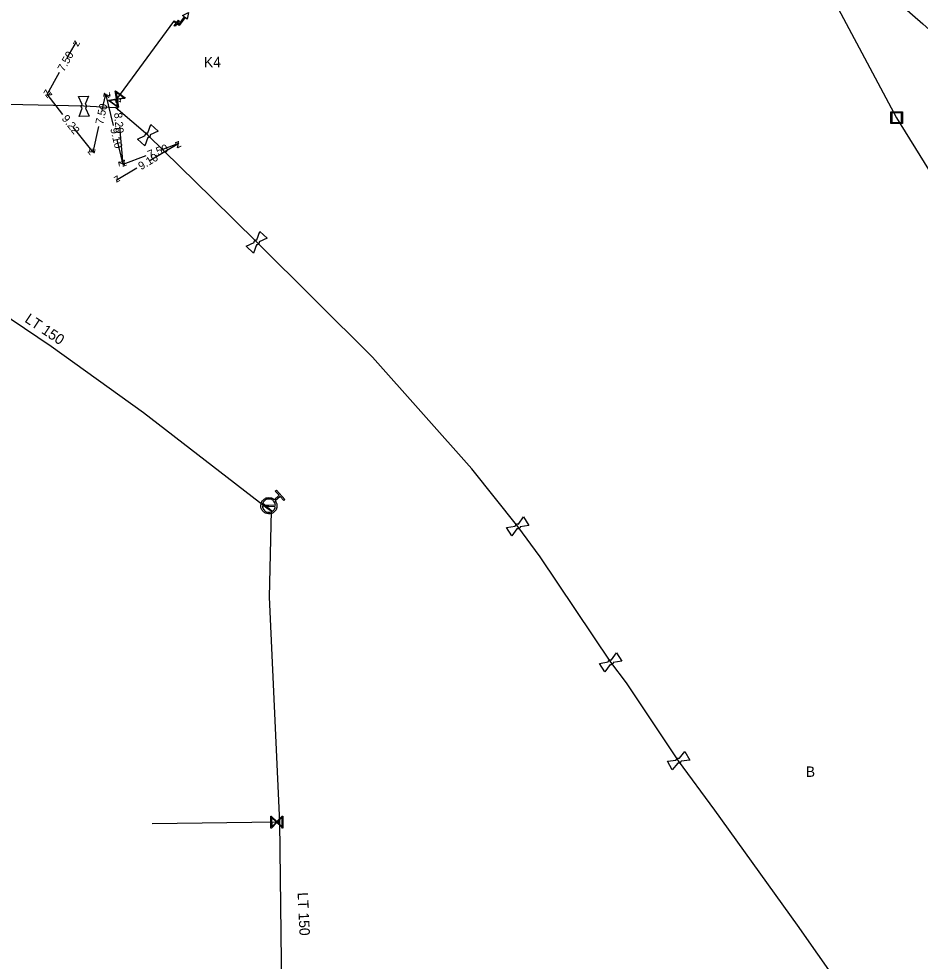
# Model space of a CAD drawing. Extents: x -643842 to -636370, y -1119190 to -1110210.
# Drawn here: x -641289.2 to -641176.7, y -1114622.1 to -1114504.4 of the extents above; entities that cross this region are included whole.
import ezdxf

# ---------------------------------------------------------------- set-up
doc = ezdxf.new("R2010")
doc.units = 0
for name, color, linetype in [('Default', 7, 'Continuous'), ('Level 10', 7, 'Continuous'), ('Level 16', 7, 'Continuous'), ('Level 18', 7, 'Continuous'), ('Level 19', 7, 'Continuous'), ('Level 20', 7, 'Continuous'), ('Level 21', 7, 'Continuous'), ('Level 23', 7, 'Continuous'), ('Level 28', 7, 'Continuous'), ('Level 32', 7, 'Continuous'), ('Level 33', 7, 'Continuous')]:
    doc.layers.add(name, color=color, linetype=linetype)

msp = doc.modelspace()

# ---------------------------------------------------------------- linework, layer by layer
at = {"layer": 'Default'}
for points in [[(-641281.31, -1114515.53), (-641281.35, -1114515.5), (-641281.38, -1114515.45), (-641281.42, -1114515.38), (-641281.42, -1114515.3), (-641281.43, -1114515.22), (-641281.39, -1114515.14), (-641281.36, -1114515.09), (-641281.32, -1114515.06)], [(-641280.92, -1114515.04), (-641280.88, -1114515.08), (-641280.85, -1114515.12), (-641280.8, -1114515.19), (-641280.8, -1114515.28), (-641280.8, -1114515.36), (-641280.84, -1114515.43), (-641280.86, -1114515.48), (-641280.9, -1114515.52)], [(-641273.43, -1114518.94), (-641273.44, -1114518.88), (-641273.42, -1114518.83), (-641273.4, -1114518.75), (-641273.35, -1114518.69), (-641273.29, -1114518.63), (-641273.21, -1114518.6), (-641273.16, -1114518.58), (-641273.11, -1114518.59)], [(-641272.81, -1114518.86), (-641272.8, -1114518.91), (-641272.81, -1114518.97), (-641272.83, -1114519.05), (-641272.89, -1114519.11), (-641272.94, -1114519.17), (-641273.02, -1114519.2), (-641273.08, -1114519.21), (-641273.13, -1114519.21)], [(-641259.83, -1114532.32), (-641259.84, -1114532.27), (-641259.83, -1114532.21), (-641259.81, -1114532.13), (-641259.76, -1114532.07), (-641259.7, -1114532.01), (-641259.62, -1114531.98), (-641259.57, -1114531.97), (-641259.51, -1114531.97)], [(-641259.21, -1114532.24), (-641259.21, -1114532.29), (-641259.22, -1114532.35), (-641259.24, -1114532.43), (-641259.29, -1114532.49), (-641259.35, -1114532.55), (-641259.43, -1114532.58), (-641259.48, -1114532.59), (-641259.53, -1114532.59)], [(-641257.2, -1114564.56), (-641256.97, -1114564.85), (-641256.99, -1114565.21), (-641257.01, -1114565.63), (-641257.31, -1114565.91), (-641257.62, -1114566.19), (-641258.03, -1114566.17), (-641258.45, -1114566.16), (-641258.73, -1114565.85), (-641259.01, -1114565.55), (-641258.99, -1114565.13), (-641258.98, -1114564.72), (-641258.67, -1114564.44), (-641258.37, -1114564.16), (-641257.95, -1114564.17), (-641257.59, -1114564.18), (-641257.32, -1114564.43)], [(-641257.18, -1114565.11), (-641257.2, -1114564.83), (-641257.39, -1114564.62), (-641257.62, -1114564.37), (-641257.96, -1114564.36), (-641258.29, -1114564.34), (-641258.54, -1114564.57), (-641258.76, -1114564.77), (-641258.8, -1114565.05)], [(-641258.8, -1114565.23), (-641258.78, -1114565.51), (-641258.59, -1114565.72), (-641258.36, -1114565.97), (-641258.02, -1114565.98), (-641257.69, -1114566), (-641257.44, -1114565.77), (-641257.23, -1114565.57), (-641257.19, -1114565.3)], [(-641227.23, -1114567.71), (-641227.22, -1114567.66), (-641227.19, -1114567.62), (-641227.15, -1114567.54), (-641227.08, -1114567.5), (-641227.01, -1114567.46), (-641226.93, -1114567.45), (-641226.87, -1114567.45), (-641226.82, -1114567.47)], [(-641226.61, -1114567.82), (-641226.62, -1114567.87), (-641226.64, -1114567.91), (-641226.69, -1114567.99), (-641226.76, -1114568.03), (-641226.83, -1114568.07), (-641226.91, -1114568.08), (-641226.96, -1114568.08), (-641227.01, -1114568.06)], [(-641215.61, -1114584.68), (-641215.61, -1114584.63), (-641215.58, -1114584.58), (-641215.54, -1114584.51), (-641215.47, -1114584.46), (-641215.4, -1114584.42), (-641215.32, -1114584.41), (-641215.26, -1114584.41), (-641215.21, -1114584.43)], [(-641214.99, -1114584.77), (-641215, -1114584.82), (-641215.03, -1114584.87), (-641215.07, -1114584.95), (-641215.14, -1114584.99), (-641215.21, -1114585.03), (-641215.29, -1114585.04), (-641215.34, -1114585.04), (-641215.39, -1114585.02)], [(-641207.13, -1114596.95), (-641207.12, -1114596.9), (-641207.09, -1114596.85), (-641207.05, -1114596.78), (-641206.97, -1114596.74), (-641206.9, -1114596.7), (-641206.82, -1114596.7), (-641206.76, -1114596.7), (-641206.71, -1114596.72)], [(-641206.52, -1114597.08), (-641206.53, -1114597.13), (-641206.55, -1114597.18), (-641206.6, -1114597.25), (-641206.67, -1114597.29), (-641206.74, -1114597.33), (-641206.83, -1114597.33), (-641206.88, -1114597.33), (-641206.93, -1114597.31)]]:
    msp.add_open_spline(points, degree=3, dxfattribs=at)
at = {"layer": 'Level 10'}
for points in [[(-641283.17, -1114509.26), (-641282.04, -1114507.24)], [(-641284.17, -1114511.07), (-641285.69, -1114513.79)], [(-641283.72, -1114516.3), (-641285.69, -1114513.79)], [(-641278.81, -1114515.79), (-641278.35, -1114513.73)], [(-641277.4, -1114517.69), (-641278.35, -1114513.73)], [(-641276.86, -1114515.78), (-641276.98, -1114514.41)], [(-641282.47, -1114517.89), (-641279.99, -1114521.04)], [(-641279.26, -1114517.81), (-641279.99, -1114521.04)], [(-641276.67, -1114517.84), (-641276.24, -1114522.58)], [(-641276.99, -1114519.43), (-641276.24, -1114522.58)], [(-641272.93, -1114522.1), (-641269.24, -1114519.89)], [(-641271.44, -1114520.74), (-641269.24, -1114519.89)], [(-641273.37, -1114521.48), (-641276.24, -1114522.58)], [(-641274.47, -1114523.02), (-641277.05, -1114524.56)]]:
    msp.add_lwpolyline(points, dxfattribs=at)
at = {"layer": 'Level 16'}
for points in [[(-641277.14, -1114513.36), (-641275.93, -1114514.25), (-641275.97, -1114514.3), (-641276.1, -1114514.32), (-641276.93, -1114514.45), (-641276.78, -1114515.41), (-641276.82, -1114515.46), (-641278.03, -1114514.58), (-641277.99, -1114514.52), (-641277.03, -1114514.38), (-641277.16, -1114513.55), (-641277.18, -1114513.42), (-641277.14, -1114513.36)], [(-641277.07, -1114513.53), (-641276.94, -1114514.36), (-641276.12, -1114514.23), (-641277.07, -1114513.53)], [(-641276.89, -1114515.3), (-641277.02, -1114514.46), (-641277.85, -1114514.59), (-641276.89, -1114515.3)], [(-641258.77, -1114564.87), (-641257.61, -1114565.82), (-641257.67, -1114565.9), (-641258.83, -1114564.94), (-641258.77, -1114564.87)], [(-641256.26, -1114603.93), (-641256.24, -1114605.43), (-641256.3, -1114605.43), (-641256.39, -1114605.34), (-641256.99, -1114604.75), (-641257.67, -1114605.45), (-641257.74, -1114605.45), (-641257.76, -1114603.95), (-641257.69, -1114603.95), (-641257, -1114604.63), (-641256.41, -1114604.02), (-641256.32, -1114603.93), (-641256.26, -1114603.93)], [(-641257.64, -1114605.29), (-641257.06, -1114604.69), (-641257.66, -1114604.1), (-641257.64, -1114605.29)], [(-641256.35, -1114604.09), (-641256.93, -1114604.69), (-641256.33, -1114605.27), (-641256.35, -1114604.09)]]:
    msp.add_lwpolyline(points, dxfattribs=at)
at = {"layer": 'Level 18'}
for points in [[(-641178.88, -1114516), (-641178.88, -1114517.45), (-641180.3, -1114517.45), (-641180.3, -1114516), (-641178.88, -1114516)], [(-641180.18, -1114516.12), (-641180.18, -1114517.33), (-641179, -1114517.33), (-641179, -1114516.12), (-641180.18, -1114516.12)]]:
    msp.add_lwpolyline(points, dxfattribs=at)
at = {"layer": 'Level 21'}
for points in [[(-641260.05, -1114373.85), (-641246.44, -1114396.73), (-641232.73, -1114420.13), (-641224.28, -1114436.22), (-641214.82, -1114454.08), (-641189.89, -1114497.4), (-641179.59, -1114516.72), (-641168.72, -1114534.34), (-641160.69, -1114546.34), (-641152.25, -1114559.28), (-641144.18, -1114571.8), (-641125.09, -1114600.83), (-641114.58, -1114615.84), (-641090.67, -1114654.64), (-641085.81, -1114661.49), (-641065.7, -1114689.7)], [(-641184.99, -1114496.55), (-641180.87, -1114500.98), (-641176.31, -1114504.98), (-641172.08, -1114508.83), (-641169.35, -1114511.67), (-641164.86, -1114516.52), (-641161.43, -1114519.48)], [(-641179.28, -1114635.67), (-641191.96, -1114617.56), (-641202.31, -1114603.19), (-641206.82, -1114597.02), (-641213.34, -1114587.28), (-641215.3, -1114584.73), (-641224.12, -1114571.57), (-641226.92, -1114567.77), (-641232.64, -1114560.55), (-641245.04, -1114546.61), (-641259.52, -1114532.28), (-641265.11, -1114526.73), (-641273.12, -1114518.9), (-641277.1, -1114515.47), (-641281.11, -1114515.29), (-641294.46, -1114514.99), (-641301.39, -1114514.66), (-641303.28, -1114514.77), (-641333.85, -1114515.53), (-641335.16, -1114515.55)], [(-641296.7, -1114534.4), (-641295.85, -1114535.55), (-641291.9, -1114540.77), (-641285.2, -1114545.26), (-641273.65, -1114553.53), (-641258.25, -1114565.42), (-641257.72, -1114565.83), (-641257.95, -1114576.59), (-641256.71, -1114603.81), (-641256.67, -1114604.68), (-641256.02, -1114660.22), (-641255.81, -1114671.46), (-641255.55, -1114675.5), (-641254.49, -1114679.67), (-641254.52, -1114685.01), (-641254.51, -1114685.66), (-641254.58, -1114705.69), (-641254.58, -1114705.72), (-641254.64, -1114722.08), (-641254.68, -1114723.44), (-641254.89, -1114729.86), (-641254.02, -1114749.54), (-641253.92, -1114751.56)]]:
    msp.add_lwpolyline(points, dxfattribs=at)
at = {"layer": 'Level 23'}
for points in [[(-641277.1, -1114514.57), (-641276.98, -1114514.41), (-641269.87, -1114504.69)], [(-641258.25, -1114565.42), (-641257.99, -1114565.17)], [(-641256.67, -1114604.68), (-641257, -1114604.69), (-641272.57, -1114604.89)]]:
    msp.add_lwpolyline(points, dxfattribs=at)
at = {"layer": 'Level 28'}
for points in [[(-641281.78, -1114514.06), (-641280.53, -1114514.02), (-641280.92, -1114515.04)], [(-641281.32, -1114515.06), (-641281.78, -1114514.06)], [(-641280.9, -1114515.52), (-641280.44, -1114516.51), (-641281.69, -1114516.56), (-641281.31, -1114515.53)], [(-641273.11, -1114518.59), (-641272.74, -1114517.56)], [(-641272.74, -1114517.56), (-641271.81, -1114518.4), (-641272.81, -1114518.86)], [(-641273.13, -1114519.21), (-641273.5, -1114520.24), (-641274.42, -1114519.4), (-641273.43, -1114518.94)], [(-641259.51, -1114531.97), (-641259.14, -1114530.94)], [(-641259.14, -1114530.94), (-641258.22, -1114531.78), (-641259.21, -1114532.24)], [(-641259.53, -1114532.59), (-641259.91, -1114533.62), (-641260.83, -1114532.78), (-641259.83, -1114532.32)], [(-641226.82, -1114567.47), (-641226.18, -1114566.58)], [(-641226.18, -1114566.58), (-641225.53, -1114567.65), (-641226.61, -1114567.82)], [(-641227.01, -1114568.06), (-641227.66, -1114568.95), (-641228.31, -1114567.88), (-641227.23, -1114567.71)], [(-641215.39, -1114585.02), (-641216.02, -1114585.92), (-641216.69, -1114584.87), (-641215.61, -1114584.68)], [(-641215.21, -1114584.43), (-641214.59, -1114583.53)], [(-641214.59, -1114583.53), (-641213.91, -1114584.58), (-641214.99, -1114584.77)], [(-641206.71, -1114596.72), (-641206.03, -1114595.86)], [(-641206.03, -1114595.86), (-641205.43, -1114596.96), (-641206.52, -1114597.08)], [(-641206.93, -1114597.31), (-641207.61, -1114598.17), (-641208.22, -1114597.08), (-641207.13, -1114596.95)]]:
    msp.add_lwpolyline(points, dxfattribs=at)
at = {"layer": 'Level 33'}
for points in [[(-641269.41, -1114504.9), (-641269.21, -1114505.05), (-641268.55, -1114504.14), (-641268.8, -1114503.96), (-641268.05, -1114503.58), (-641268.19, -1114504.4), (-641268.45, -1114504.22), (-641269.18, -1114505.22), (-641269.49, -1114505), (-641269.71, -1114505.3), (-641269.81, -1114505.23), (-641269.59, -1114504.93), (-641269.89, -1114504.71), (-641269.81, -1114504.61), (-641269.51, -1114504.83), (-641269.29, -1114504.53), (-641269.19, -1114504.6), (-641269.41, -1114504.9)], [(-641257.32, -1114564.43), (-641256.72, -1114563.87), (-641257.19, -1114563.37), (-641257.05, -1114563.24), (-641255.99, -1114564.39), (-641256.13, -1114564.51), (-641256.59, -1114564.01), (-641257.2, -1114564.56)], [(-641258.8, -1114565.05), (-641257.18, -1114565.11)], [(-641257.19, -1114565.3), (-641258.8, -1114565.23)]]:
    msp.add_lwpolyline(points, dxfattribs=at)

# ---------------------------------------------------------------- texts
at = {"layer": 'Level 10'}
for s, rotation, p in [('z', 60.9024, (-641281.85, -1114507.92)), ('7.50', 60.9024, (-641283.59, -1114511.05)), ('z', 240.9024, (-641285.88, -1114513.11)), ('z', 128.1534, (-641284.99, -1114513.88)), ('z', 77.3386, (-641277.97, -1114514.32)), ('z', 103.3873, (-641277.74, -1114514.1)), ('7.50', 77.3386, (-641278.71, -1114517.63)), ('z', 95.1755, (-641276.44, -1114514.86)), ('9.22', 308.1534, (-641283.93, -1114516.84)), ('8.20', 275.1755, (-641277.33, -1114516.12)), ('9.10', 283.3873, (-641277.82, -1114518.1)), ('z', 30.8515, (-641269.41, -1114520.58)), ('z', 20.9915, (-641269.52, -1114520.54)), ('z', 308.1534, (-641280.69, -1114520.96)), ('z', 257.3386, (-641280.37, -1114520.45)), ('7.50', 20.9915, (-641272.91, -1114521.84)), ('z', 283.3872, (-641276.84, -1114522.21)), ('z', 275.1754, (-641276.78, -1114522.13)), ('z', 200.9914, (-641275.95, -1114521.93)), ('9.10', 30.8515, (-641273.95, -1114523.29)), ('z', 210.8515, (-641276.88, -1114523.87))]:
    msp.add_text(s, height=1, rotation=rotation, dxfattribs=at).set_placement(p)
at = {"layer": 'Level 19'}
msp.add_text('B', height=1.3, dxfattribs=at).set_placement((-641190.94, -1114599.04))
at = {"layer": 'Level 20'}
for rotation, p in [(326.1602, (-641288.59, -1114542.15)), (272.6188, (-641254.41, -1114613.49))]:
    msp.add_text('LT 150', height=1.3, rotation=rotation, dxfattribs=at).set_placement(p)
at = {"layer": 'Level 32'}
msp.add_text('K4', height=1.3, rotation=1, dxfattribs=at).set_placement((-641266.1, -1114510.44))

doc.saveas('drawing.dxf')
